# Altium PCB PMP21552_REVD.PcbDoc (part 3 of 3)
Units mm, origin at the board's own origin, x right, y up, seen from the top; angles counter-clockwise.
Board outline 45.05 x 86.02 mm, 4 copper layers (Top Layer, Signal Layer 1, Signal Layer 2, Bottom Layer), stack 1.006 mm thick; 146 components, 80 nets, 395 pads, 82 vias.
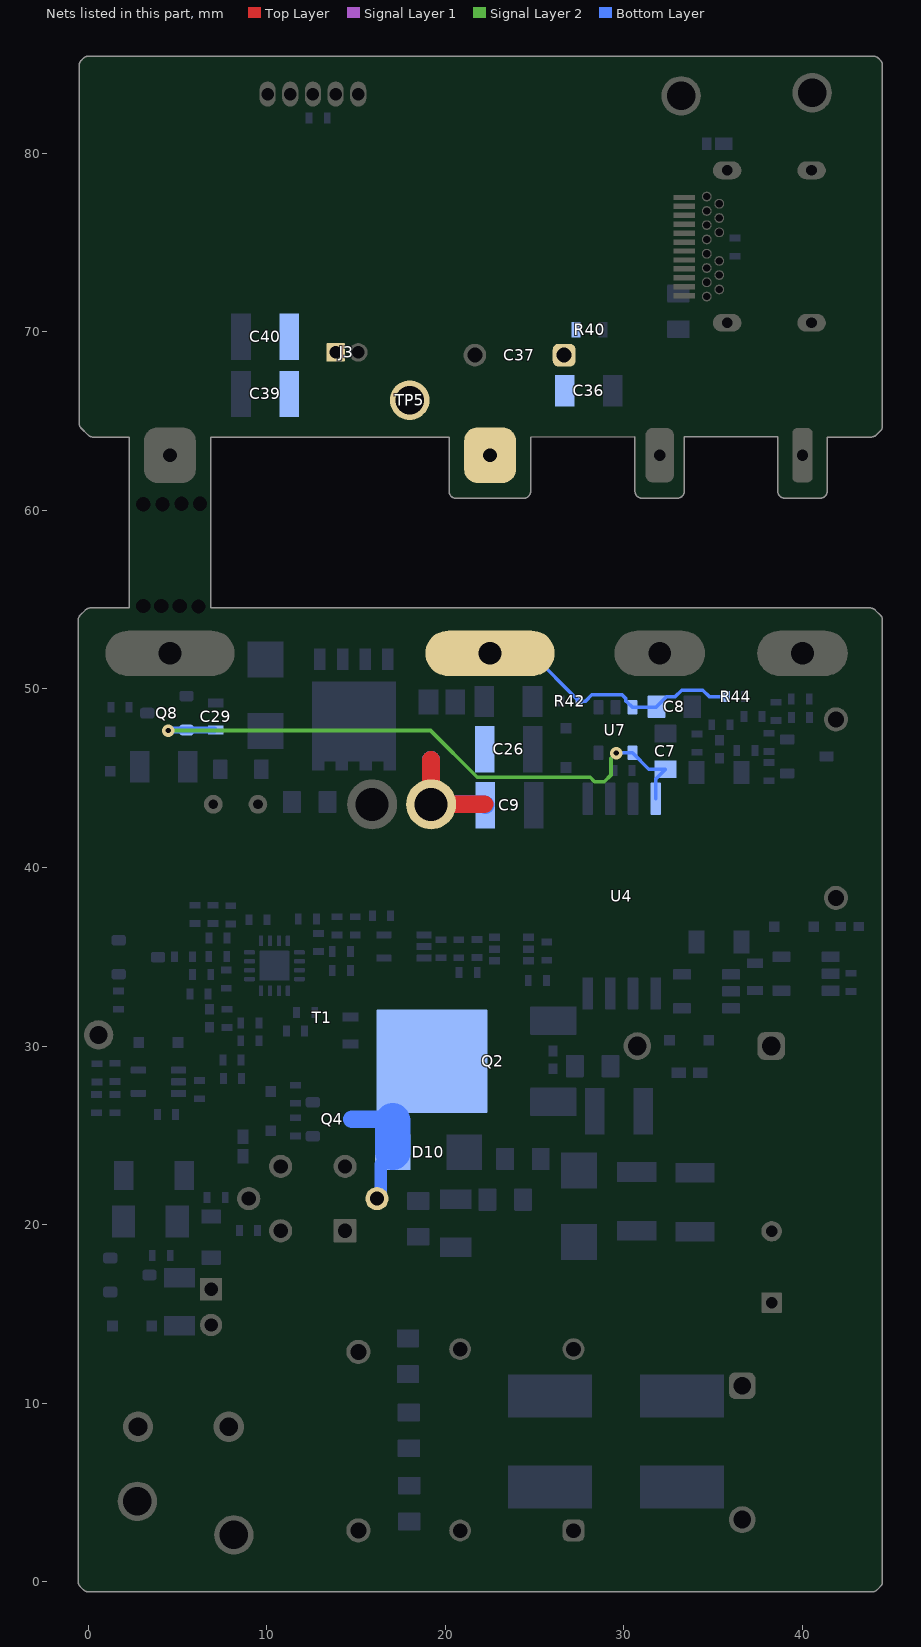
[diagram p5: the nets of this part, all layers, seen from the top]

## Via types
v1: diameter 0.7, hole 0.3, Top Layer to Bottom Layer, 77 vias
v2: diameter 0.5, hole 0.2, Top Layer to Bottom Layer, 5 vias

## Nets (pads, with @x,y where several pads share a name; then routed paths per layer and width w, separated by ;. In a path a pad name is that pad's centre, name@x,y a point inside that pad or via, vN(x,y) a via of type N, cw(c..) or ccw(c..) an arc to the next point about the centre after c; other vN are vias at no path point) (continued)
Vdd_sec: C7.1 C29.2 Q8.2 U4.8 U7.4 | length 35.1
  Signal Layer 2 w0.2: v1(4.48,47.675) 19.167,47.675 21.792,45.05 28.106,45.05 28.356,44.8 28.894,44.8 29.275,45.181 29.275,46.126 v1(29.564,46.415)
  Bottom Layer w0.2: v1(29.564,46.415) 29.574,46.425 U7.4@30.475,46.425 31.398,45.502 C7.1@32.325,45.502 31.78,44.957 U4.8@31.78,43.85
  Bottom Layer w0.4: v1(4.48,47.675) 4.505,47.7 Q8.2@5.5,47.7 C29.2@7.053,47.7
VN: C8.1 C9.1 C26.1 pad.0@22.5,52 R42.1 R44.1 T1.A U7.3 | length 31.9
  Top Layer w1: 19.2,46.027 T1.A@19.2,43.542 22.198,43.542
  Signal Layer 1 w1: T1.A@19.2,43.542 T1.A@19.442,43.542 ; 19.2,46.027 19.2,43.784 T1.A@19.442,43.542 ; 22.033,43.542 T1.A@19.442,43.542
  Bottom Layer w0.2: pad.0@22.5,52 24.8,52 R42.1@27.483,49.317 27.847,49.317 28.205,49.675 29.895,49.675 30.1,49.47 30.1,49.317 30.133,49.317 U7.3@30.475,48.975 31.8,48.975 C8.1@31.825,49 32.4,49.575 32.88,49.575 33.23,49.925 34.42,49.925 34.77,49.575 R44.1@35.742,49.575
  Bottom Layer w1: 19.2,46.027 T1.A@19.2,43.542 22.198,43.542 C9.1@22.24,43.5
VN2: C36.1 C37.1 C39.1 C40.1 J3.1 pad.2@22.5,63.096 R40.2 TP5.1
Vswn: D10.2 Q2.2 Q4.3 T1.2 | length 7.2
  Bottom Layer w0.152: T1.2@16.169,21.457 T1.2@16.169,21.628
  Bottom Layer w0.3: T1.2@16.169,21.457 T1.2@16.387,21.675 ; D10.2@16.387,23.387 D10.2@17.05,24.05
  Bottom Layer w0.7: T1.2@16.387,21.675 D10.2@16.387,23.387
  Bottom Layer w1: Q4.3@14.775,25.9 16.95,25.9 17.05,25.8
  Bottom Layer w2: D10.2@17.05,24.05 17.05,25.8
pads on no net: J1.A2 J1.A3 J1.A8 J1.A10 J1.A11 J1.B2 J1.B3 J1.B8 J1.B10 J1.B11 T1.3 U2.17@10.425,34.5

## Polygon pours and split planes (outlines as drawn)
PGND on Bottom Layer "BOTTOM_LAYER_PGND_P180" (solid, remove dead copper, pour order 180): 31.023,9.075 31.023,-0.7 44.683,-0.7 44.683,9.075
NetC1_1 on Bottom Layer "BOTTOM_LAYER_NETC1_1_P178" (solid, remove dead copper, pour order 178): 30.847,17.025 30.847,9.15 44.482,9.15 44.482,17.025
SGND2 on Bottom Layer "BOTTOM_LAYER_SGND2_P170" (solid, remove dead copper, pour order 170): -0.573,85.449 -0.573,60.689 44.625,60.689 44.625,85.449
VBUS on Bottom Layer "BOTTOM_LAYER_VBUS_P168" (solid, remove dead copper, pour order 168): 8.2,85.525 8.2,71.525 35,71.525 35,85.525
VN2 on Bottom Layer "BOTTOM_LAYER_VN2_P162" (solid, remove dead copper, pour order 162): 10.575,71.2 10.575,60.682 27.9,60.682 27.9,71.2
SGND on Bottom Layer "BOTTOM_LAYER_SGND_P142" (solid, remove dead copper, pour order 142): 6.625,52.134 6.625,42.625 29.965,42.625 30.091,52.134
SGND on Bottom Layer "BOTTOM_LAYER_SGND_P140" (solid, remove dead copper, pour order 140): 2.989,53.987 2.989,45.078 44.111,45.077 44.229,53.987
SGND on Bottom Layer "BOTTOM_LAYER_SGND_P138" (solid, remove dead copper, pour order 138): -0.318,53.948 -0.318,44.275 37.151,44.275 37.28,53.948
VN on Bottom Layer "BOTTOM_LAYER_VN_P130" (solid, remove dead copper, pour order 130): 18.475,48.127 18.475,42.125 23.875,42.125 23.875,48.125
NetC33_2 on Bottom Layer "BOTTOM_LAYER_NETC33_2_P128" (solid, remove dead copper, pour order 128): 12.362,50.575 12.362,42.625 18.125,42.625 18.125,50.575
PGND on Bottom Layer "BOTTOM_LAYER_PGND_P106" (solid, remove dead copper, pour order 106): 10.175,36.477 10.175,17.575 44.19,17.575 44.19,36.477
PGND on Bottom Layer "BOTTOM_LAYER_PGND_P104" (solid, remove dead copper, pour order 104): -0.318,38 -0.318,13 18.325,13 18.325,38
NetC10_2 on Bottom Layer "BOTTOM_LAYER_NETC10_2_P100" (solid, remove dead copper, pour order 100): 36.725,37.25 36.725,32.5 44.19,32.5 44.19,37.25
Vbulk on Bottom Layer "BOTTOM_LAYER_VBULK_P098" (solid, remove dead copper, pour order 98): 36.175,31.825 36.175,18.05 44.482,18.05 44.482,31.825
NetC10_2 on Bottom Layer "BOTTOM_LAYER_NETC10_2_P096" (solid, remove dead copper, pour order 96): 24.65,24.75 24.65,29.6 28.999,29.6 29.001,24.75
Vbulk on Bottom Layer "BOTTOM_LAYER_VBULK_P094" (solid, remove dead copper, pour order 94): 12.515,21.35 12.515,18.025 44.227,18.025 44.227,21.35
PGND on Signal Layer 2 "SIGNAL_LAYER_2_PGND_P182" (solid, remove dead copper, pour order 182): 31.04,18.362 31.04,-0.558 44.577,-0.558 44.577,18.362
SGND2 on Signal Layer 2 "SIGNAL_LAYER_2_SGND2_P172" (solid, remove dead copper, pour order 172): -0.568,85.623 -0.568,60.689 44.482,60.689 44.482,85.623
SGND on Signal Layer 2 "SIGNAL_LAYER_2_SGND_P148" (solid, remove dead copper, pour order 148): 5.224,52.364 5.224,42.619 29.925,42.619 29.925,52.364
SGND on Signal Layer 2 "SIGNAL_LAYER_2_SGND_P146" (solid, remove dead copper, pour order 146): 13.907,53.948 13.907,45.153 44.175,45.153 44.175,53.948
SGND on Signal Layer 2 "SIGNAL_LAYER_2_SGND_P144" (solid, remove dead copper, pour order 144): -0.318,53.948 -0.318,44.3 29.95,44.3 29.95,53.948
PGND on Signal Layer 2 "SIGNAL_LAYER_2_PGND_P110" (solid, remove dead copper, pour order 110): 11.517,36.462 11.517,17.542 44.482,17.542 44.482,36.462
PGND on Signal Layer 2 "SIGNAL_LAYER_2_PGND_P108" (solid, remove dead copper, pour order 108): -0.318,38.05 -0.318,13 16.106,13 16.225,38.05
NetC10_2 on Signal Layer 2 "SIGNAL_LAYER_2_NETC10_2_P102" (solid, remove dead copper, pour order 102): 24.675,34.492 24.675,28.425 39.401,28.425 39.401,34.492
PGND on Signal Layer 1 "SIGNAL_LAYER_1_PGND_P184" (solid, remove dead copper, pour order 184): 31.04,18.196 31.04,-0.707 44.482,-0.707 44.482,18.196
SGND2 on Signal Layer 1 "SIGNAL_LAYER_1_SGND2_P174" (solid, remove dead copper, pour order 174): -0.823,85.423 -0.823,60.682 44.482,60.682 44.482,85.423
SGND on Signal Layer 1 "SIGNAL_LAYER_1_SGND_P154" (solid, remove dead copper, pour order 154): 5.227,52.223 5.227,42.6 29.89,42.6 29.89,52.223
SGND on Signal Layer 1 "SIGNAL_LAYER_1_SGND_P152" (solid, remove dead copper, pour order 152): 13.852,53.973 13.852,45.153 44.12,45.153 44.12,53.973
SGND on Signal Layer 1 "SIGNAL_LAYER_1_SGND_P150" (solid, remove dead copper, pour order 150): -0.456,53.948 -0.456,44.325 29.813,44.325 29.813,53.948
VN on Signal Layer 1 "SIGNAL_LAYER_1_VN_P134" (solid, remove dead copper, pour order 134): 17.65,53.948 17.65,42.65 27.125,42.65 27.125,53.948
no net on Signal Layer 1 "SIGNAL_LAYER_1_NONET_P132" (solid, remove dead copper, pour order 132): 26.5,53.775
PGND on Signal Layer 1 "SIGNAL_LAYER_1_PGND_P116" (solid, remove dead copper, pour order 116): 12.575,36.421 12.575,17.518 44.482,17.518 44.482,36.421
PGND on Signal Layer 1 "SIGNAL_LAYER_1_PGND_P114" (solid, remove dead copper, pour order 114): -0.318,38.075 -0.318,13.075 16.914,13.075 16.914,38.075
PGND on Top Layer "TOP_LAYER_PGND_P186" (solid, remove dead copper, pour order 186): 31.04,17.518 31.04,-0.618 44.391,-0.618 44.391,17.518
SGND2 on Top Layer "TOP_LAYER_SGND2_P176" (solid, remove dead copper, pour order 176): -0.65,85.55 -0.65,60.682 44.482,60.682 44.482,85.55
VN2 on Top Layer "TOP_LAYER_VN2_P166" (solid, remove dead copper, pour order 166): 10.5,71.15 10.5,60.689 27.925,60.689 27.925,71.15
VBUS on Top Layer "TOP_LAYER_VBUS_P164" (solid, remove dead copper, pour order 164): 8.25,85.449 8.25,71.1 33.929,71.1 33.929,85.449
SGND on Top Layer "TOP_LAYER_SGND_P160" (solid, remove dead copper, pour order 160): 6.527,53.975 6.527,42.6 29.925,42.6 29.925,53.975
SGND on Top Layer "TOP_LAYER_SGND_P158" (solid, remove dead copper, pour order 158): 12.8,53.942 12.8,45.185 44.35,45.185 44.35,53.942
SGND on Top Layer "TOP_LAYER_SGND_P156" (solid, remove dead copper, pour order 156): -0.418,53.942 -0.418,44.375 29.962,44.375 29.962,53.942
VN on Top Layer "TOP_LAYER_VN_P136" (solid, remove dead copper, pour order 136): 17.657,53.975 17.657,42.575 27.125,42.575 27.125,53.975
PGND on Top Layer "TOP_LAYER_PGND_P126" (solid, remove dead copper, pour order 126): 11.467,36.421 11.467,17.527 44.227,17.521 44.227,36.421
PGND on Top Layer "TOP_LAYER_PGND_P124" (solid, remove dead copper, pour order 124): -0.409,38.05 -0.325,13 16.875,13 16.875,38.05
Vbulk on Top Layer "TOP_LAYER_VBULK_P122" (solid, remove dead copper, pour order 122): 12.575,24.075 12.575,17.525 43.909,17.525 43.909,24.075
Vbulk on Top Layer "TOP_LAYER_VBULK_P120" (solid, remove dead copper, pour order 120): 33.127,31.701 33.127,17.518 44.19,17.518 44.19,31.701
no net on Top Layer "TOP_LAYER_NONET_P118" (solid, remove dead copper, pour order 118): 30.759,16

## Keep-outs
Top Layer:
  rectangle: 8.35,27.825 8.775,29.525
  lines w0.254: 8.6,29.225 9.083,29.225 9.558,29.7 9.558,30.45 9.533,30.475 9.733,30.475 10.16,30.902 10.16,33.308
Signal Layer 1:
  rectangle: 8.3,27.825 8.775,29.575
  lines w0.254: 8.55,29.175 8.6,29.225 9.083,29.225 9.558,29.7 9.558,30.3 10.16,30.902 10.16,33.308
Signal Layer 2:
  rectangle: 8.35,27.825 8.775,29.525
  lines w0.254: 8.599,29.225 9.083,29.225 9.558,29.7 ; 9.958,30.7 10.16,30.902 10.16,31.425 ; 10.16,32.525 10.16,33.308
Keep-Out Layer:
  text ".Layer_Name" at 14.656,-21.806 h1.52

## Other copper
Top Layer:
  text ".Layer_Name" at 14.656,-21.806 h1.52
Bottom Layer:
  text ".Layer_Name" at 14.656,-21.806 h1.52

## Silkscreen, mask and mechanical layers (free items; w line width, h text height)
Top Overlay:
  text "NEUT" at 5.969,4.826 h1.02
  text "LINE" at 1.016,1.27 h1.02
  text ".Layer_Name" at 14.656,-21.806 h1.52
Bottom Overlay:
  rectangle: 20.6,-0.325 28.22,2.215
  text "PMP21552 D" at 43.875,0.425 h2.75
  text ".Layer_Name" at 14.656,-21.806 h1.52
Top Paste:
  text ".Layer_Name" at 14.656,-21.806 h1.52
Bottom Paste:
  text ".Layer_Name" at 14.656,-21.806 h1.52
Top Solder:
  text ".Layer_Name" at 14.656,-21.806 h1.52
  text ".Layer_Name" at 14.656,-21.806 h1.52
Bottom Solder:
  text ".Layer_Name" at 14.656,-21.806 h1.52
Drill Guide:
  text ".Layer_Name" at 14.656,-21.806 h1.52
M1 Board Outline:
  drawing of 215 lines, arcs and shapes, not listed
  text ".Layer_Name" at 14.656,-21.806 h1.52
M2 Board Dimensions:
  rectangle: 3.175,-10.16 12.7,-6.985
  rectangle: 0,-6.985 3.175,-3.81
  lines w0.178: 0,-6.985 25.4,-6.985 ; 3.175,-10.16 3.175,-3.81 ; 6.35,-10.16 6.35,-3.81 ; 12.7,-10.16 12.7,-3.81 ; 19.05,-10.16 19.05,-3.81 ; 0,-10.16 0,-3.81 25.4,-3.81 25.4,-10.16 0,-10.16
  text ".Layer_Name" at 14.656,-21.806 h1.52
M3 3D STEP Top:
  text ".Layer_Name" at 14.656,-21.806 h1.52
M4 3D STEP Bottom:
  text ".Layer_Name" at 14.656,-21.806 h1.52
M5 Assembly Top:
  lines w0.254: -7.417,-23.626 160.223,-23.626 ; -7.417,-18.462 160.274,-18.462 ; -7.417,-13.297 -7.417,-28.791 94.31,-28.791 160.274,-28.791 160.274,-13.297 -7.404,-13.297 -7.404,-28.791 32.614,-28.791 ; 55.194,-28.791 55.194,-13.297 ; 87.376,-18.462 87.376,-13.297 ; 108.712,-18.462 108.712,-13.297 ; 124.511,-28.956 124.511,-23.804
  text "COMPONENTS MARKED 'DNP' SHOULD NOT BE POPULATED." at 29.299,-8.09 h1.52
  text "ASSEMBLY VARIANT:" at 29.286,-11.024 h1.52
  text ".VariantName" at 55.601,-11.024 h1.52
  text "PCB VIEWED FROM TOP SIDE" at -5.804,-16.654 h1.52
  text "BOARD #:" at 57.099,-16.654 h1.52
  text ".PRJ_Number" at 70.955,-16.654 h1.52
  text "REV:" at 92.405,-16.654 h1.52
  text ".PCB_Rev" at 99.809,-16.654 h1.52
  text "SVN REV:" at 113.69,-16.654 h1.52
  text ".VersionControl_RevNumber" at 126.543,-16.654 h1.52
  text "TID #:" at 57.099,-21.819 h1.52
  text ".TID" at 70.955,-21.819 h1.52
  text "PLOT NAME =" at -5.804,-27.034 h1.52
  text ".plot_File_Name" at 14.656,-27.034 h1.52
  text "GENERATED    :" at 57.15,-27.034 h1.52
  text ".Print_Date" at 79.235,-27.034 h1.52
  text ".Print_Time" at 97.752,-27.034 h1.52
  text "TEXAS INSTRUMENTS" at 129.87,-27.034 h1.52
M6 Assembly Bottom:
  lines w0.254: -7.429,-18.474 160.261,-18.474 ; -7.379,-23.639 160.261,-23.639 ; 28.334,-28.969 28.334,-23.817 ; 44.133,-18.474 44.133,-13.31 ; 65.468,-18.474 65.468,-13.31 ; 97.65,-28.804 97.65,-13.31 ; 120.231,-28.804 160.249,-28.804 160.249,-13.31 -7.429,-13.31 -7.429,-28.804 58.534,-28.804 160.261,-28.804 160.261,-13.31
  text "COMPONENTS MARKED 'DNP' SHOULD NOT BE POPULATED." at 154.991,-8.077 h1.52
  text ".VariantName" at 128.473,-11.024 h1.52
  text "ASSEMBLY VARIANT:" at 154.864,-11.024 h1.52
  text ".VersionControl_RevNumber" at 26.302,-16.667 h1.52
  text "SVN REV:" at 39.154,-16.667 h1.52
  text ".PCB_Rev" at 53.035,-16.667 h1.52
  text "REV:" at 60.439,-16.667 h1.52
  text ".PRJ_Number" at 81.89,-16.667 h1.52
  text "BOARD #:" at 95.745,-16.667 h1.52
  text "PCB VIEWED FROM BOTTOM SIDE" at 158.648,-16.667 h1.52
  text ".TID" at 81.89,-21.831 h1.52
  text "TID #:" at 95.745,-21.831 h1.52
  text "TEXAS INSTRUMENTS" at 22.974,-27.047 h1.52
  text ".Print_Time" at 55.093,-27.047 h1.52
  text ".Print_Date" at 73.609,-27.047 h1.52
  text "GENERATED    :" at 95.694,-27.047 h1.52
  text ".plot_File_Name" at 138.189,-27.047 h1.52
  text "PLOT NAME =" at 158.648,-27.047 h1.52
M9 Title Sheet:
  drawing of 57 lines, arcs and shapes, not listed
  text "1" at 18.792,204.127 h1.78
  text "2" at 82.182,204.127 h1.78
  text "3" at 145.411,204.127 h1.78
  text "4" at 209.08,204.127 h1.78
  text "5" at 272.555,204.127 h1.78
  text "6" at 336.182,204.127 h1.78
  text "A" at -10.579,175.095 h1.78
  text "A" at 365.341,175.095 h1.78
  text "B" at -10.579,114.643 h1.78
  text "B" at 365.341,114.643 h1.78
  text "C" at -10.579,54.318 h1.78
  text "C" at 365.341,54.318 h1.78
  text "PROJECT TITLE:" at 288.125,7.048 h1.14
  text ".PRJ_Title" at 289.395,3.662 h1.78
  text "DESIGNED FOR:" at 288.125,-0.597 h1.14
  text ".PRJ_Customer" at 289.395,-4.153 h1.78
  text "D" at -10.579,-5.88 h1.78
  text "D" at 365.341,-5.88 h1.78
  text "FILE NAME:" at 288.125,-8.217 h1.14
  text ".PCB_File_Name_No_Path" at 289.395,-11.265 h1.78
  text "Texas Instruments (TI) and/or its licensors do not warrant the accuracy or completeness of this specification" at 161.9,-15.376 h1.14
  text "ENGINEER:" at 288.125,-15.583 h1.14
  text "LAYOUT BY:" at 326.352,-15.583 h1.14
  text "or any information contained therein. TI and/or its licensors do not warrant that this design will meet" at 160.757,-18.237 h1.14
  text ".PRJ_Engineer" at 289.395,-19.52 h1.78
  text ".PCB_Layout" at 327.635,-19.52 h1.78
  text "the specifications, will be suitable for your application or fit for any particular purpose, or will operate in" at 160.757,-21.099 h1.14
  text ".Layer_Name" at 14.656,-21.806 h1.52
  text "ALTIUM DESIGNER VERSION:" at 326.352,-23.457 h1.14
  text "an implementation. TI and/or its licensors do not warrant that the design is production worthy. You should" at 160.757,-23.961 h1.14
  text "completely validate and test your design implementation to confirm the system functionality for your application." at 161.9,-26.822 h1.14
  text ".print_Scale" at 289.395,-26.843 h1.78
  text ".Application_BuildNumber" at 327.635,-26.843 h1.78
  text "1" at 18.792,-32.093 h1.78
  text "2" at 82.182,-32.093 h1.78
  text "3" at 145.411,-32.093 h1.78
  text "4" at 209.08,-32.093 h1.78
  text "5" at 272.555,-32.093 h1.78
  text "6" at 336.182,-32.093 h1.78
M10 Fab Notes:
  drawing of 189 lines, arcs and shapes, not listed
  text "DESIGN INFORMATION" at 314.503,161.447 h1.52
  text "MIN. TRACK WIDTH:" at 298.131,158.091 h1.52
  text "8" at 325.976,158.091 h1.52
  text "MIL" at 329.907,158.091 h1.52
  text "MIN. CLEARANCE:" at 298.131,154.938 h1.52
  text "0.2" at 324.452,154.938 h1.52
  text "mm" at 329.907,154.938 h1.52
  text "MIN. VIA PAD SIZE:" at 298.131,151.785 h1.52
  text "24" at 325.214,151.785 h1.52
  text "MIL" at 329.907,151.785 h1.52
  text "0.05mm (2MIL)" at 315.784,148.486 h1.52
  text "MINIMUM ANNULAR RING" at 289.769,148.277 h1.52
  text "EXTERNAL" at 333.768,148.277 h1.52
  text "PER" at 294.849,145.48 h1.52
  text "IPC-D-275 CLASS 2 LEVEL C" at 300.437,145.48 h1.52
  text "MIL, HOLES" at 338.238,142.928 h1.52
  text "+/-" at 328.27,142.709 h1.52
  text "+/-" at 349.961,142.709 h1.52
  text "REGISTRATION TOLERANCES:" at 289.769,142.682 h1.52
  text "METAL" at 320.243,142.682 h1.52
  text "5" at 334.879,142.683 h1.52
  text "3" at 356.037,142.683 h1.52
  text "MIL" at 358.99,142.682 h1.52
  text "HOLE SIZE TOLERANCE (UNLESS OTHERWISE SPECIFIED):" at 289.769,140.185 h1.52
  text "+/-" at 349.961,140.112 h1.52
  text "3" at 356.037,140.085 h1.52
  text "MIL" at 358.99,140.085 h1.52
  text "MATERIAL:" at 287.87,136.589 h1.52
  text "FR-4 High Tg" at 312.926,133.324 h1.52
  text "X" at 309.257,133.122 h1.52
  text "FR-408" at 298.563,133.007 h1.52
  text "OTHER" at 336.358,133.007 h1.52
  text "62 MIL (1.6mm) +/-10%" at 306.694,129.374 h1.52
  text "X" at 336.296,129.235 h1.52
  text "40MIL" at 348.615,129.184 h1.83
  text "THICKNESS:" at 289.769,129.165 h1.52
  text "OTHER" at 339.33,129.165 h1.52
  text "TOLERANCE:" at 289.769,125.652 h1.52
  text "X" at 311.314,125.652 h1.52
  text "ANSI IPC-6012 TYPE 3 CLASS 2" at 315.836,125.652 h1.52
  text "OTHER +/-" at 315.835,121.989 h1.52
  text "BOW & TWIST:" at 289.769,118.302 h1.52
  text "X" at 311.314,118.302 h1.52
  text "ANSI IPC-6012 TYPE 3 CLASS 2" at 315.836,118.302 h1.52
  text "OTHER +/-" at 315.835,114.576 h1.52
  text "DRILLING:" at 287.87,111.258 h1.52
  text "NC_DRILL FILES" at 332.599,108.586 h1.52
  text "REFERENCE:" at 289.769,108.486 h1.52
  text "X" at 306.463,108.484 h1.52
  text "AS SHOWN" at 310.984,108.486 h1.52
  text "X" at 329.348,108.486 h1.52
  text "OTHER" at 340.168,104.873 h1.52
  text "PTH COPPER THICKNESS:" at 289.761,104.783 h1.52
  text "X" at 318.697,104.783 h1.52
  text "20-30 um" at 321.948,104.783 h1.52
  text "BOARD FINISH:" at 287.87,101.034 h1.52
  text "SILKSCREEN:" at 291.812,98.237 h1.52
  text "X" at 316.14,98.237 h1.52
  text "TOP" at 319.112,98.237 h1.52
  text "X" at 329.094,98.237 h1.52
  text "BOTTOM" at 332.091,98.237 h1.52
  text "SILKSCREEN COLOR:" at 291.812,94.295 h1.52
  text "X" at 316.115,94.295 h1.52
  text "WHITE" at 319.112,94.295 h1.52
  text "OTHER" at 332.091,94.295 h1.52
  text "X" at 319.442,90.652 h1.52
  text "GREEN" at 322.439,90.652 h1.52
  text "OTHER" at 338.136,90.652 h1.52
  text "SOLDER RESIST COLOR:" at 291.812,90.477 h1.52
  text "X" at 319.442,86.734 h1.52
  text "MATTE" at 322.439,86.734 h1.52
  text "SEMI-GLOSS" at 338.125,86.717 h1.52
  text "IMMERSION GOLD (ENIG)" at 314.819,82.345 h1.52
  text "ENEPIG" at 348.793,82.162 h1.52
  text "SURFACE FINISH:" at 287.87,82.136 h1.52
  text "X" at 310.298,82.136 h1.52
  text "IMM. TIN/SILVER OR EQUIV" at 296.24,78.649 h1.52
  text "OTHER" at 332.599,78.549 h1.52
  text "ARRAY/PANEL:" at 287.87,74.602 h1.52
  text "CUT AND TRIM PER M1 BOARD OUTLINE" at 314.819,74.393 h1.52
  text "N.C. ROUTE" at 314.819,70.94 h1.52
  text "X" at 332.295,70.94 h1.52
  text "V. SCORE" at 336.816,70.94 h1.52
  text "CERTIFICATION:" at 287.87,67.66 h1.52
  text "MATERIALS AND WORKMANSHIP FOR ALL PCBS" at 306.285,67.66 h1.52
  text "TO MEET OR EXCEED THE REQUIREMENTS OF:" at 306.285,65.271 h1.52
  text "X" at 297.078,62.003 h1.52
  text "ANSI IPC-A-600F CLASS ->" at 300.329,62.003 h1.52
  text "X" at 342.188,62.003 h1.52
  text "2" at 344.982,62.003 h1.52
  text "1" at 336.981,61.965 h1.52
  text "3" at 353.973,61.965 h1.52
  text "X" at 317.702,58.252 h1.52
  text "RoHS" at 320.953,58.252 h1.52
  text "OTHER" at 337.321,58.252 h1.52
  text "PER ORDER" at 347.407,58.252 h1.52
  text "ALL BOARDS MUST MEET OR EXCEED UL94-V0 REQUIREMENTS." at 288.569,54.345 h1.52
  text "PCB MUST BEAR THE UL94V-0 UL REGISTERED MATERIAL ID NUMBER" at 288.569,51.397 h1.52
  text "ADDITIONAL REQUIREMENTS:" at 287.87,47.094 h1.52
  text "MICROSECTION:" at 289.769,44.373 h1.52
  text "YES" at 312.775,44.373 h1.52
  text "REQUIRED" at 334.657,40.707 h1.52
  text "BARE BOARD ELEC. TEST:" at 289.769,40.634 h1.52
  text "NONE" at 322.935,40.634 h1.52
  text "X" at 331.66,40.634 h1.52
  text "PER ORDER" at 349.693,40.634 h1.52
  text "XX MIL VIAS REQUIRE NON-CONDUCTIVE FILL AND PLANARIZE" at 294.04,35.428 h1.5
  text "XX MIL VIAS REQUIRE CONDUCTIVE FILL AND PLANARIZE" at 294.243,32.787 h1.52
  text "OUTER XX MIL VIAS REQUIRE 50 OHM SINGLE-ENDED IMPEDANCE" at 294.218,28.637 h1.47
  text "LAYER 2 & 3 (INNER LAYERS) XX MIL WIDE, XX MIL SPACE / TRACES REQUIRE 100 OHM DIFFERENTIAL IMPEDANCE" at 294.015,22.65 h1.52
  text ".Layer_Name" at 14.656,-21.806 h1.52
M11 Gerber Information:
  lines w0.254: -7.417,-23.626 160.223,-23.626 ; -7.417,-18.462 160.274,-18.462 ; -7.417,-13.297 -7.417,-28.791 94.31,-28.791 160.274,-28.791 160.274,-13.297 -7.404,-13.297 -7.404,-28.791 32.614,-28.791 ; 55.194,-28.791 55.194,-13.297 ; 87.376,-18.462 87.376,-13.297 ; 108.712,-18.462 108.712,-13.297 ; 124.511,-28.956 124.511,-23.804
  text "ALL ARTWORK VIEWED FROM TOP SIDE" at -5.804,-16.654 h1.52
  text "BOARD #:" at 57.099,-16.654 h1.52
  text ".PRJ_Number" at 70.955,-16.654 h1.52
  text "REV:" at 92.405,-16.654 h1.52
  text ".PCB_Rev" at 99.809,-16.654 h1.52
  text "SVN REV:" at 113.69,-16.654 h1.52
  text ".VersionControl_RevNumber" at 126.543,-16.654 h1.52
  text "LAYER NAME =" at -5.804,-21.806 h1.52
  text "TID #:" at 57.099,-21.819 h1.52
  text ".TID" at 70.955,-21.819 h1.52
  text "PLOT NAME =" at -5.804,-27.034 h1.52
  text ".plot_File_Name" at 14.656,-27.034 h1.52
  text "GENERATED    :" at 57.15,-27.034 h1.52
  text ".Print_Date" at 79.235,-27.034 h1.52
  text ".Print_Time" at 97.752,-27.034 h1.52
  text "TEXAS INSTRUMENTS" at 129.87,-27.034 h1.52
M12 Stackup:
  drawing of 295 lines, arcs and shapes, not listed
  text "Layer" at 249.015,199.542 h1.52
  text "Name" at 259.427,199.542 h1.52
  text "Material" at 283.296,199.542 h1.52
  text "Thickness" at 305.134,199.542 h1.52
  text "Constant" at 321.64,199.542 h1.52
  text "Board Layer Stack" at 336.115,199.542 h1.52
  text "1" at 249.015,196.494 h1.52
  text "Top Overlay" at 259.427,196.494 h1.52
  text "2" at 249.015,193.446 h1.52
  text "Top Solder" at 259.427,193.446 h1.52
  text "Solder Resist" at 283.296,193.446 h1.52
  text "0.40mil" at 305.134,193.446 h1.52
  text "3.5" at 321.64,193.446 h1.52
  text "3" at 249.015,190.398 h1.52
  text "Top Layer" at 259.427,190.398 h1.52
  text "Copper" at 283.296,190.398 h1.52
  text "1.40mil" at 305.134,190.398 h1.52
  text "4" at 249.015,187.35 h1.52
  text "Dielectric 1" at 259.427,187.35 h1.52
  text "FR-4" at 283.296,187.35 h1.52
  text "8.00mil" at 305.134,187.35 h1.52
  text "4.2" at 321.64,187.35 h1.52
  text "5" at 249.015,184.302 h1.52
  text "Signal Layer 1" at 259.427,184.302 h1.52
  text "Copper" at 283.296,184.302 h1.52
  text "1.40mil" at 305.134,184.302 h1.52
  text "6" at 249.015,181.254 h1.52
  text "Dielectric 2" at 259.427,181.254 h1.52
  text "FR-4" at 283.296,181.254 h1.52
  text "18.00mil" at 305.134,181.254 h1.52
  text "4.2" at 321.64,181.254 h1.52
  text "7" at 249.015,178.206 h1.52
  text "Signal Layer 2" at 259.427,178.206 h1.52
  text "Copper" at 283.296,178.206 h1.52
  text "1.40mil" at 305.134,178.206 h1.52
  text "8" at 249.015,175.158 h1.52
  text "Dielectric 3" at 259.427,175.158 h1.52
  text "FR-4" at 283.296,175.158 h1.52
  text "8.00mil" at 305.134,175.158 h1.52
  text "4.2" at 321.64,175.158 h1.52
  text "9" at 249.015,172.11 h1.52
  text "Bottom Layer" at 259.427,172.11 h1.52
  text "Copper" at 283.296,172.11 h1.52
  text "1.40mil" at 305.134,172.11 h1.52
  text "10" at 249.015,169.062 h1.52
  text "Bottom Solder" at 259.427,169.062 h1.52
  text "Solder Resist" at 283.296,169.062 h1.52
  text "0.40mil" at 305.134,169.062 h1.52
  text "3.5" at 321.64,169.062 h1.52
  text "11" at 249.015,166.014 h1.52
  text "Bottom Overlay" at 259.427,166.014 h1.52
  text ".Layer_Name" at 14.656,-21.806 h1.52
M13 Component Bodies Top:
  text ".Layer_Name" at 14.656,-21.806 h1.52
M14 Component Bodies Bottom:
  text ".Layer_Name" at 14.656,-21.806 h1.52
M15 Courtyards Top:
  text ".Layer_Name" at 14.656,-21.806 h1.52
M16 Courtyards Bottom:
  text ".Layer_Name" at 14.656,-21.806 h1.52
Drill Drawing:
  drawing of 184 lines, arcs and shapes, not listed
  text "Symbol" at 136.159,93.319 h1.83
  text "Quantity" at 143.793,93.319 h1.83
  text "Finished Hole Size" at 152.226,93.319 h1.83
  text "Plated" at 168.395,93.319 h1.83
  text "Hole Type" at 174.977,93.319 h1.83
  text "Drill Layer Pair" at 184.506,93.319 h1.83
  text "Hole Tolerance" at 202.904,93.319 h1.83
  text "8" at 143.793,90.162 h1.52
  text "31.50mil (0.800mm)" at 152.226,90.162 h1.52
  text "NPTH" at 168.395,90.162 h1.52
  text "Round" at 174.977,90.162 h1.52
  text "Top Layer - Bottom Layer" at 184.506,90.162 h1.52
  text "5" at 143.793,87.004 h1.52
  text "7.87mil (0.200mm)" at 152.226,87.004 h1.52
  text "PTH" at 168.395,87.004 h1.52
  text "Round" at 174.977,87.004 h1.52
  text "Top Layer - Bottom Layer" at 184.506,87.004 h1.52
  text "77" at 143.793,83.846 h1.52
  text "11.81mil (0.300mm)" at 152.226,83.846 h1.52
  text "PTH" at 168.395,83.846 h1.52
  text "Round" at 174.977,83.846 h1.52
  text "Top Layer - Bottom Layer" at 184.506,83.846 h1.52
  text "14" at 143.793,80.688 h1.52
  text "15.75mil (0.400mm)" at 152.226,80.688 h1.52
  text "PTH" at 168.395,80.688 h1.52
  text "Round" at 174.977,80.688 h1.52
  text "Top Layer - Bottom Layer" at 184.506,80.688 h1.52
  text "1" at 143.793,77.531 h1.52
  text "21.65mil (0.550mm)" at 152.226,77.531 h1.52
  text "PTH" at 168.395,77.531 h1.52
  text "Round" at 174.977,77.531 h1.52
  text "Top Layer - Bottom Layer" at 184.506,77.531 h1.52
  text "1" at 143.793,74.373 h1.52
  text "21.65mil (0.550mm)" at 152.226,74.373 h1.52
  text "PTH" at 168.395,74.373 h1.52
  text "Round" at 174.977,74.373 h1.52
  text "Top Layer - Bottom Layer" at 184.506,74.373 h1.52
  text "2" at 143.793,71.215 h1.52
  text "25.00mil (0.635mm)" at 152.226,71.215 h1.52
  text "PTH" at 168.395,71.215 h1.52
  text "Round" at 174.977,71.215 h1.52
  text "Top Layer - Bottom Layer" at 184.506,71.215 h1.52
  text "H" at 135.517,70.962 h1.4
  text "2" at 143.793,68.058 h1.52
  text "25.59mil (0.650mm)" at 152.226,68.058 h1.52
  text "PTH" at 168.395,68.058 h1.52
  text "Round" at 174.977,68.058 h1.52
  text "Top Layer - Bottom Layer" at 184.506,68.058 h1.52
  text "C" at 135.517,67.804 h1.4
  text "5" at 143.793,64.9 h1.52
  text "27.56mil (0.700mm)" at 152.226,64.9 h1.52
  text "PTH" at 168.395,64.9 h1.52
  text "Round" at 174.977,64.9 h1.52
  text "Top Layer - Bottom Layer" at 184.506,64.9 h1.52
  text "2" at 143.793,61.742 h1.52
  text "28.00mil (0.711mm)" at 152.226,61.742 h1.52
  text "PTH" at 168.395,61.742 h1.52
  text "Round" at 174.977,61.742 h1.52
  text "Top Layer - Bottom Layer" at 184.506,61.742 h1.52
  text "2" at 143.793,58.584 h1.52
  text "29.53mil (0.750mm)" at 152.226,58.584 h1.52
  text "PTH" at 168.395,58.584 h1.52
  text "Round" at 174.977,58.584 h1.52
  text "Top Layer - Bottom Layer" at 184.506,58.584 h1.52
  text "D" at 135.517,58.331 h1.4
  text "2" at 143.793,55.427 h1.52
  text "30.00mil (0.762mm)" at 152.226,55.427 h1.52
  text "PTH" at 168.395,55.427 h1.52
  text "Round" at 174.977,55.427 h1.52
  text "Top Layer - Bottom Layer" at 184.506,55.427 h1.52
  text "F" at 135.517,55.173 h1.4
  text "6" at 143.793,52.269 h1.52
  text "31.50mil (0.800mm)" at 152.226,52.269 h1.52
  text "PTH" at 168.395,52.269 h1.52
  text "Round" at 174.977,52.269 h1.52
  text "Top Layer - Bottom Layer" at 184.506,52.269 h1.52
  text "G" at 135.517,52.015 h1.4
  text "4" at 143.793,49.111 h1.52
  text "32.00mil (0.813mm)" at 152.226,49.111 h1.52
  text "PTH" at 168.395,49.111 h1.52
  text "Round" at 174.977,49.111 h1.52
  text "Top Layer - Bottom Layer" at 184.506,49.111 h1.52
  text "2" at 143.793,45.953 h1.52
  text "33.47mil (0.850mm)" at 152.226,45.953 h1.52
  text "PTH" at 168.395,45.953 h1.52
  text "Round" at 174.977,45.953 h1.52
  text "Top Layer - Bottom Layer" at 184.506,45.953 h1.52
  text "4" at 143.793,42.796 h1.52
  text "35.43mil (0.900mm)" at 152.226,42.796 h1.52
  text "PTH" at 168.395,42.796 h1.52
  text "Round" at 174.977,42.796 h1.52
  text "Top Layer - Bottom Layer" at 184.506,42.796 h1.52
  text "3" at 143.793,39.638 h1.52
  text "39.37mil (1.000mm)" at 152.226,39.638 h1.52
  text "PTH" at 168.395,39.638 h1.52
  text "Round" at 174.977,39.638 h1.52
  text "Top Layer - Bottom Layer" at 184.506,39.638 h1.52
  text "4" at 143.793,36.48 h1.52
  text "41.34mil (1.050mm)" at 152.226,36.48 h1.52
  text "PTH" at 168.395,36.48 h1.52
  text "Round" at 174.977,36.48 h1.52
  text "Top Layer - Bottom Layer" at 184.506,36.48 h1.52
  text "A" at 135.517,36.227 h1.4
  text "5" at 143.793,33.323 h1.52
  text "63.00mil (1.600mm)" at 152.226,33.323 h1.52
  text "PTH" at 168.395,33.323 h1.52
  text "Round" at 174.977,33.323 h1.52
  text "Top Layer - Bottom Layer" at 184.506,33.323 h1.52
  text "2" at 143.793,30.165 h1.52
  text "72.84mil (1.850mm)" at 152.226,30.165 h1.52
  text "PTH" at 168.395,30.165 h1.52
  text "Round" at 174.977,30.165 h1.52
  text "Top Layer - Bottom Layer" at 184.506,30.165 h1.52
  text "B" at 135.517,29.911 h1.4
  text "4" at 143.793,27.007 h1.52
  text "23.62mil (0.600mm)" at 152.226,27.007 h1.52
  text "PTH" at 168.395,27.007 h1.52
  text "Slot" at 174.977,27.007 h1.52
  text "Top Layer - Bottom Layer" at 184.506,27.007 h1.52
  text "2" at 143.793,23.849 h1.52
  text "50.00mil (1.270mm)" at 152.226,23.849 h1.52
  text "PTH" at 168.395,23.849 h1.52
  text "Slot" at 174.977,23.849 h1.52
  text "Top Layer - Bottom Layer" at 184.506,23.849 h1.52
  text "E" at 135.517,23.596 h1.4
  text "2" at 143.793,20.692 h1.52
  text "50.00mil (1.270mm)" at 152.226,20.692 h1.52
  text "PTH" at 168.395,20.692 h1.52
  text "Slot" at 174.977,20.692 h1.52
  text "Top Layer - Bottom Layer" at 184.506,20.692 h1.52
  text "159 Total" at 143.793,17.534 h1.52
  text "Slot definitions :" at 136.159,15.324 h1.52
  text "Routed Path Length" at 147.607,15.324 h1.52
  text "= Calculated from tool start centre position to tool end centre position." at 161.317,15.324 h1.52
  text "Hole Length" at 147.607,14.06 h1.52
  text "= Routed Path Length + Tool Size = Slot length as defined in the PCB layout" at 156.242,14.06 h1.52
  text ".Layer_Name" at 14.656,-21.806 h1.52
Mechanical 17:
  text ".Layer_Name" at 14.656,-21.806 h1.52
Mechanical 18:
  text ".Layer_Name" at 14.656,-21.806 h1.52
Mechanical 19:
  text ".Layer_Name" at 14.656,-21.806 h1.52

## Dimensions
0,-10.16 to 25.4,-10.16 on M2 Board Dimensions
